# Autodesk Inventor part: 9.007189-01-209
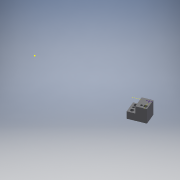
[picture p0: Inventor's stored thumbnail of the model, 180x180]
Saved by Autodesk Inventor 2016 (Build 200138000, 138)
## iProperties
Created: 2013-01
Part Number: 9.007189-01-209
Material: 1.1730
Document SubType Name: Modeling
Density: 7.84 g/cm^3
Description: Aufnahme
Appearance: Hellgrau
B: 76
D: 61
L: 58
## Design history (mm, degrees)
sketch "Lage Bezugsachse (z.B. Mitte Sucher) in x und y von Z-Achse "
  geometry: L1 (284, 0)-(298, 0) reference; L2 (0, -21.3)-(0, 276.9) reference; C1 r 5 at (462, 71)
  constraints: 4 end point, 1 centre point, 1 horizontal, 1 vertical, 4 other
  dimensions: "d20" = 462 distance from line of C1.centre L2; "d21" = 71 distance from line of L1 C1.centre; "d27" = 10 diameter of C1
node "Basisachse_Schnittlinie XZ und YZ-Ebene-Bauteil"
node "AE (Winkel 112,378578059 grd)_1"
node "AE (Winkel 90 grd)_1"
node "AE (Winkel 90 grd)_2"
  node "X-Achse Schnittlinie zwischen XY und XZ-Ebene Bauteil"
workpoint "Arbeitspunkt_zum_Best._des_Koord._systems"
node "UK (Versatz -56 mm)_1"
node "OK (Versatz 61 mm)_1"
sketch "Rohmass"
  geometry: L1 (-36, 50)-(22, 50); L2 (22, 50)-(22, -26); L3 (22, -26)-(-36, -26); L4 (-36, -26)-(-36, 50); L5 (-233.6, 0)-(236.8, 0); L6 (0, -259.12)-(0, 158.36); L7 (0, -616.15)-(0, 723.825) reference; L8 (-550.608, 0)-(639.628, 0) reference
  constraints: 12 end point, 2 collinear, 2 parallel, 1 horizontal, 1 perpendicular
  dimensions: "d28" = 36 distance between parallel lines of L4 L6; "d29" = 22 distance between parallel lines of L2 L6; "d30" = 58 distance between parallel lines of L2 L4 (derived); "d31" = 50 distance between parallel lines of L5 L1; "d32" = 26 distance between parallel lines of L3 L5; "d33" = 76 distance between parallel lines of L3 L1 (derived)
extrude "Rohklotz" new body sketch "Rohmass" stored distance "d34" = 10; taper "d35" = 0 deg
node "NP1"
node "NP2"
node "NP3"
node "NP4"
node "HP1"
node "HP2"
node "HP3"
node "HP4"
node "yz-rechts"
node "yz-links"
node "xz-oben"
node "xz-unten"
sketch "Skizze21"
  geometry: L1 (-36, 50)-(22, 50) reference; L2 (-36, -26)-(-36, 50) reference; L3 (22, -26)-(-36, -26) reference; L4 (22, 50)-(22, -26) reference
feature "EKL_ABMESSUNGEN" sketch "Skizze21" dims "d96" = 0.001, "d97" = 0
sketch "Skizze26"
  geometry: L1 (-177.96, 0)-(456.996, 0) reference; L2 (0, -192.087)-(0, 571.419) reference; L3 (22, -228.425)-(22, 577.476) reference; L4 (-36, -228.425)-(-36, 577.476) reference; L5 (-192.922, 50)-(459.49, 50) reference; L6 (22, 50)-(-36, 50); L7 (-36, 50)-(-36, 18); L8 (-36, 18)-(22, 18); L9 (22, 18)-(22, 50)
  constraints: 8 end point, 3 point on line, 2 parallel, 1 horizontal, 1 perpendicular
  dimensions: "d154" = 18 distance between parallel lines of L1 L8
extrude "Extrusion11" cut sketch "Skizze26" distance "d155" = 30; taper "d156" = 0 deg
sketch "KM"
  geometry: L1 (-22, 52.5)-(-22, 17.5); L2 (-39.5, 35)-(-4.5, 35); L3 (-22, 2.5)-(-22, -32.5); L4 (-39.5, -15)-(-4.5, -15); L5 (10, 52.5)-(10, 17.5); L6 (-7.5, 35)-(27.5, 35); L7 (-211.063, 0)-(462.513, 0) reference; L8 (0, -272.485)-(0, 584.819) reference; C1 r 7.5 at (-22, 35); C2 r 7.5 at (10, 35); C3 r 7.5 at (-22, -15); 6 further points
  constraints: 12 end point, 7 coincident, 7 midpoint, 5 equal length, 3 centre point, 3 perpendicular, 3 vertical, 2 equal radius
  dimensions: "d51" = 15 diameter of C1; "d52" = 35 distance of L1.start L1.end; "d98" = 10 distance between parallel lines of L8 L5; "d100" = 35 distance between parallel lines of L7 L6; "d102" = 15 distance between parallel lines of L7 L4; "d103" = 35 distance between parallel lines of L7 L2; "d104" = 22 distance between parallel lines of L8 L3; "d105" = 22 distance between parallel lines of L8 L1
hole "3x Zapfen Ø15 mm  x 41 mm  tief, Ø9 mm  durch_1" sketch "KM" diameter "d56" = 9; stored, may be unused: countersink angle "d60" = 90 deg, drill point angle "d62" = 118 deg; dims "d57" = 6, "d58" = 15, "d59" = 41 (computed from D), "d61" = 8
sketch "H7"
  geometry: L1 (-5, 54.5)-(-5, 19.5); L2 (-22, 17.5)-(-22, -17.5); L3 (-22.5, 37)-(12.5, 37); L4 (-39.5, 0)-(-4.5, 0); L5 (-189.94, 0)-(458.993, 0) reference; L6 (0, -221.182)-(0, 576.268) reference; C1 r 4 at (-5, 37); C2 r 4 at (-22, 0); 4 further points
  constraints: 8 end point, 4 coincident, 4 midpoint, 3 equal length, 2 centre point, 2 perpendicular, 2 vertical, 1 equal radius
  dimensions: "d80" = 8 diameter of C1; "d81" = 35 distance of L1.start L1.end; "d110" = 0 distance between parallel lines of L5 L4; "d111" = 37 distance between parallel lines of L5 L3; "d112" = 5 distance between parallel lines of L6 L1; "d113" = 22 distance between parallel lines of L6 L2
hole "2x Ø8 mm  durch_1" sketch "H7" diameter "d163" = 8; stored, may be unused: countersink angle "d167" = 90 deg, drill point angle "d169" = 118 deg; dims "d164" = 6, "d165" = 4, "d166" = 2, "d168" = 8
sketch "Skizze20"
  geometry: C1 r 4 at (86, -138) reference; C2 r 4 at (-5, 37) reference; C3 r 4 at (-22, 0) reference
hole "2x Ø10 mm  x 36 mm tief_1" sketch "Skizze20" at (-5, 37), (-22, 0) diameter "d170" = 10; stored, may be unused: countersink angle "d174" = 90 deg, drill point angle "d176" = 118 deg; dims "d171" = 6, "d172" = 4, "d173" = 2, "d175" = 36 (computed from D)
sketch "Skizze27"
  geometry: L1 (-52.5, 10)-(-17.5, 10) reference; L2 (15, -39.5)-(15, -4.5) reference; 2 further points
  constraints: 2 point on line
node "Volumenkörper1"
node "Volumenkörpern"
node "Oberflächenkörpern"
node "Projizierte Kontur4"
node "Flächen1"
other parameters: "B" = 76 (= d33) [user parameter], "D" = 61 (= d26) [user parameter; used in 2 equation terms], "L" = 58 (= d30) [user parameter], "d23" = 90 deg, "d24" = 90 deg, "d25" = -56, "d26" = 61, "d36" = 19.61376, "d147" = 0, "d148" = 0, "d149" = 0, "d150" = 0, "d151" = 0, "d152" = 0, "V1" = 74 [user parameter]
